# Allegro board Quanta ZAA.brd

Outline 244.9 x 198.7 mm; copper layers: TOP, SVCC, IN1, IN2, SGND, BOTTOM. Coordinates in mm from the lower left corner of the outline.

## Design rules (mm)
constraint set DEFAULT: min track width 0.127
net group DFP-S4W4.5(4.5)-2B: nets HDMI_DDCCLK_SW HDMI_DDCDATA_SW
net group DFP-S4W4.5(4.5)-T2B: nets HDMI_DDCCLK_MB HDMI_DDCDATA_MB
net group DFP-S4W4.5-T: nets USBP0+_R USBP0-_R
net group DFP-S4W4.5-TB: nets USBP0+_C USBP0-_C
net group DFP-S5W5.5(5.5)-2B: nets LAN_XTAL2 RTC_X1
net group DFP-S10W5(5.5: nets VCORE_SENSE VCORESS_SENSE
net group DFP-S20(10)W16(18)-T2B: nets VGA_VCCSENSE VGA_VSSSENSE
net group W5(5)-T2B: nets CPU_DRAMRST# DDR3_DRAMRST#
net group W5(5)-T12B: nets M_A_DQS8 M_A_DQS#8
net group W5.5(5.5)-T12B: nets DMIC_CLK_L DMIC_DAT_L
net group W12-T12B: nets PCIE_RCOMPN PCIE_RCOMPP
net group W25-T12B: nets +3V_RTC VCCRTC_2
net group DFP-S4(4)W4.5(4.5)-2B: nets AUX_CH_N AUX_CH_P C_PEG_TX0 C_PEG_TX1 C_PEG_TX2 C_PEG_TX3 C_PEG_TX#0 C_PEG_TX#1 C_PEG_TX#2 C_PEG_TX#3 CLK_PCIE_LANN CLK_PCIE_LANP CLK_PCIE_VGA CLK_PCIE_VGA# CLK_PCIE_WLANN CLK_PCIE_WLANP CRT_AUXN CRT_AUXP CRT_TXN0 CRT_TXN1 CRT_TXP0 CRT_TXP1 DDI2_AUXN DDI2_AUXP DDI2_TXN0 DDI2_TXN1 DDI2_TXP0 DDI2_TXP1 EDP_AUX#_C EDP_AUX_C EDP_AUXN EDP_AUXP EDP_TXN0 EDP_TXN0_C EDP_TXN1 EDP_TXN1_C EDP_TXN2 EDP_TXN2_C EDP_TXN3 EDP_TXN3_C EDP_TXP0 EDP_TXP0_C EDP_TXP1 EDP_TXP1_C EDP_TXP2 EDP_TXP2_C EDP_TXP3 EDP_TXP3_C INT_HDMICLK+ INT_HDMICLK+_C_R INT_HDMICLK- INT_HDMICLK-_C_R INT_HDMITX0N INT_HDMITX0N_C_R INT_HDMITX0P INT_HDMITX0P_C_R INT_HDMITX1N INT_HDMITX1N_C_R INT_HDMITX1P INT_HDMITX1P_C_R INT_HDMITX2N INT_HDMITX2N_C_R INT_HDMITX2P INT_HDMITX2P_C_R LANE0_N LANE0_P LANE1_N LANE1_P NGFF_SSD_CLK NGFF_SSD_CLK# NGFF_SSD_CLK#_C NGFF_SSD_CLK_C PCIE_RX5+_LAN PCIE_RX5+_LAN_C PCIE_RX5-_LAN PCIE_RX5-_LAN_C PCIE_RX6+_WLAN PCIE_RX6-_WLAN PCIE_TX5+ PCIE_TX5+_LAN PCIE_TX5- PCIE_TX5-_LAN PCIE_TX6+ PCIE_TX6+_WLAN PCIE_TX6- PCIE_TX6-_WLAN PEG_RX0 PEG_RX1 PEG_RX2 PEG_RX3 PEG_RX#0 PEG_RX#1 PEG_RX#2 PEG_RX#3 PEG_RXN0_C PEG_RXN1_C PEG_RXN2_C PEG_RXN3_C PEG_RXP0_C PEG_RXP1_C PEG_RXP2_C PEG_RXP3_C PEG_TX0 PEG_TX1 PEG_TX2 PEG_TX3 PEG_TX#0 PEG_TX#1 PEG_TX#2 PEG_TX#3 SATA_RXN0 SATA_RXN1 SATA_RXN1_C SATA_RXN3/PEG_RXN9_L0 SATA_RXN3/PEG_RXN9_L0_N SATA_RXN3/PEG_RXN10_L1 SATA_RXN3/PEG_RXN10_L1_N SATA_RXP0 SATA_RXP1 SATA_RXP1_C SATA_RXP3/PEG_RXP9_L0 SATA_RXP3/PEG_RXP9_L0_N SATA_RXP3/PEG_RXP10_L1 SATA_RXP3/PEG_RXP10_L1_N SATA_TXN0 SATA_TXN1 SATA_TXN1_C SATA_TXN3/PEG_TXN9_L0 SATA_TXN3/PEG_TXN9_L0_N SATA_TXN3/PEG_TXN10_L1 SATA_TXN3/PEG_TXN10_L1_N SATA_TXP0 SATA_TXP1 SATA_TXP1_C SATA_TXP3/PEG_TXP9_L0 SATA_TXP3/PEG_TXP9_L0_N SATA_TXP3/PEG_TXP10_L1 SATA_TXP3/PEG_TXP10_L1_N USBP0+ USBP0- USBP1+ USBP1- USBP2+ USBP2- USBP3+ USBP3- USBP4+ USBP4- USBP6+ USBP6+_R USBP6- USBP6-_R
net group DFP-S4(4)W4.5(4.5)-T2B: nets M_B_CLK0 M_B_CLK0# M_B_CLK1 M_B_CLK1# USB2_TYPC_7N_C USB2_TYPC_7P_C USB3_RXN0 USB3_RXN0_R USB3_RXN1 USB3_RXN1_R USB3_RXN2 USB3_RXN3 USB3_RXP0 USB3_RXP0_R USB3_RXP1 USB3_RXP1_R USB3_RXP2 USB3_RXP3 USB3_TXN0 USB3_TXN0_C USB3_TXN0_R USB3_TXN1 USB3_TXN1_C USB3_TXN1_R USB3_TXN2 USB3_TXN3 USB3_TXP0 USB3_TXP0_C USB3_TXP0_R USB3_TXP1 USB3_TXP1_C USB3_TXP1_R USB3_TXP2 USB3_TXP3 USB3_TYPC_RX2N_C USB3_TYPC_RX2N_C_RE USB3_TYPC_RX2N_RE USB3_TYPC_RX2P_C USB3_TYPC_RX2P_C_RE USB3_TYPC_RX2P_RE USB3_TYPC_RX3N_C USB3_TYPC_RX3N_C_RE USB3_TYPC_RX3N_RE USB3_TYPC_RX3P_C USB3_TYPC_RX3P_C_RE USB3_TYPC_RX3P_RE USB3_TYPC_TX2N_C USB3_TYPC_TX2N_C_RE USB3_TYPC_TX2N_R USB3_TYPC_TX2N_RE USB3_TYPC_TX2P_C USB3_TYPC_TX2P_C_RE USB3_TYPC_TX2P_R USB3_TYPC_TX2P_RE USB3_TYPC_TX3N_C USB3_TYPC_TX3N_C_RE USB3_TYPC_TX3N_R USB3_TYPC_TX3N_RE USB3_TYPC_TX3P_C USB3_TYPC_TX3P_C_RE USB3_TYPC_TX3P_R USB3_TYPC_TX3P_RE USBP1+_R USBP1-_R USBP7+ USBP7- USBP8+_PI3 USBP8+_R_PI3 USBP8-_PI3 USBP8-_R_PI3
net group DFP-S4(4)W4.5(4.5)-T12B: nets M_A_CLK0 M_A_CLK0# M_A_CLK1 M_A_CLK1#
net group DFP-S4.5(4.5)W5(5)-T2B: nets M_B_DQS0 M_B_DQS1 M_B_DQS2 M_B_DQS3 M_B_DQS4 M_B_DQS5 M_B_DQS6 M_B_DQS7 M_B_DQS#0 M_B_DQS#1 M_B_DQS#2 M_B_DQS#3 M_B_DQS#4 M_B_DQS#5 M_B_DQS#6 M_B_DQS#7
net group DFP-S4.5(4.5)W5(5)-T12B: nets M_A_DQS0 M_A_DQS1 M_A_DQS2 M_A_DQS3 M_A_DQS4 M_A_DQS5 M_A_DQS6 M_A_DQS7 M_A_DQS#0 M_A_DQS#1 M_A_DQS#2 M_A_DQS#3 M_A_DQS#4 M_A_DQS#5 M_A_DQS#6 M_A_DQS#7
net group DFP-S4.5(4.5)W5.5(5.5)-T12B: nets VMA_CLK0 VMA_CLK0# VMA_CLK1 VMA_CLK1# VMA_WCK01 VMA_WCK01# VMA_WCK23 VMA_WCK23# VMA_WCK45 VMA_WCK45# VMA_WCK67 VMA_WCK67# VMB_CLK0 VMB_CLK0# VMB_CLK1 VMB_CLK1# VMB_WCK01 VMB_WCK01# VMB_WCK23 VMB_WCK23# VMB_WCK45 VMB_WCK45# VMB_WCK67 VMB_WCK67#
net group DFP-S4W4.5-B: nets SATA_RXN0_C SATA_RXP0_C SATA_TXN0_C SATA_TXP0_C
net group DFP-S6W5(5.5)-T2B: nets 2ND_MBCLK 2ND_MBDATA CLK_SCLK CLK_SDATA GFX_SCL GFX_SDA I2C0_SCL I2C0_SDA I2C1_SCL I2C1_SCL_C I2C1_SDA I2C1_SDA_C I2C_TP_SCL_R I2C_TP_SDA_R MBCLK MBDATA N17046941 N17047425 PCH_MBCLK0_R PCH_MBDAT0_R SMB_ME1_CLK SMB_ME1_DAT TPCLK TPCLK_R TPDATA TPDATA_R
net group DFP-S7.5(7)W4(4)-2B: nets MDI_0+ MDI_0- MDI_1+ MDI_1- MDI_2+ MDI_2- MDI_3+ MDI_3-
net group DFP-S7.5(7)W4(4)-T2B: nets INT_HDMICLK+_C INT_HDMICLK-_C INT_HDMITX0N_C INT_HDMITX0P_C INT_HDMITX1N_C INT_HDMITX1P_C INT_HDMITX2N_C INT_HDMITX2P_C LAN_MX0+ LAN_MX0- LAN_MX1+ LAN_MX1- LAN_MX2+ LAN_MX2- LAN_MX3+ LAN_MX3-
net group DFP-S10W5(5.5)-T2B: nets VCCGT_SENSE VSA_SENSE VSASS_SENSE VSSGT_SENSE
net group DFP-S15W5.5(5.5)-2B: nets LAN_XTALI RTC_X2 XTAL24_IN XTAL24_OUT XTAL27_IN XTAL27_OUT
net group GND: nets GND
net group W4.5(4.5)-T12B: nets ACZ_SDIN HDA_BCLK_R HDA_RST#_R HDA_SDO_R HDA_SYNC_R HDMI_MB_HPD HDMI_MB_HPD_R HP_DET_CN INT_HDMI_HPD PCH_AZ_CODEC_BITCLK PCH_AZ_CODEC_RST# PCH_AZ_CODEC_SDIN0 PCH_AZ_CODEC_SDOUT PCH_AZ_CODEC_SYNC SD_CLK_R SP1 SP2 SP3 SP3=SD_CLK=MS_D0 SP4 SP5 SP6 SP6=SD_D2=MS_CLK SP7 SP8 USBCOMP
net group W4.5-T2B: nets CLK_PCIE_LAN_REQ# CLK_PCIE_REQ0# CLK_PCIE_REQ2# CLK_PCIE_REQ4# CLK_PCIE_REQ5# CLK_PEGA_REQ# PCIE_CLKREQ_WLAN# PCIE_REQ_LAN#_R PEX_CLKREQ# WLAN_CLKREQ#
net group W5(5.5)-2B: nets CPU_THRMTRIP# CRT_B1 CRT_BLU CRT_G1 CRT_GRE CRT_R1 CRT_RED ISL95857_SCLK ISL95857_SDA
net group W5(5.5)-T2B: nets CRTHSYNC CRTVSYNC HSYNC IMVP_PWRGD LPC_LAD0 LPC_LAD0_C LPC_LAD1 LPC_LAD1_C LPC_LAD2 LPC_LAD2_C LPC_LAD3 LPC_LAD3_C LPC_LFRAME# LPC_LFRAME#_C M_B_DQ0 M_B_DQ1 M_B_DQ2 M_B_DQ3 M_B_DQ4 M_B_DQ5 M_B_DQ6 M_B_DQ7 M_B_DQ8 M_B_DQ9 M_B_DQ10 M_B_DQ11 M_B_DQ12 M_B_DQ13 M_B_DQ14 M_B_DQ15 M_B_DQ16 M_B_DQ17 M_B_DQ18 M_B_DQ19 M_B_DQ20 M_B_DQ21 M_B_DQ22 M_B_DQ23 M_B_DQ24 M_B_DQ25 M_B_DQ26 M_B_DQ27 M_B_DQ28 M_B_DQ29 M_B_DQ30 M_B_DQ31 M_B_DQ32 M_B_DQ33 M_B_DQ34 M_B_DQ35 M_B_DQ36 M_B_DQ37 M_B_DQ38 M_B_DQ39 M_B_DQ40 M_B_DQ41 M_B_DQ42 M_B_DQ43 M_B_DQ44 M_B_DQ45 M_B_DQ46 M_B_DQ47 M_B_DQ48 M_B_DQ49 M_B_DQ50 M_B_DQ51 M_B_DQ52 M_B_DQ53 M_B_DQ54 M_B_DQ55 M_B_DQ56 M_B_DQ57 M_B_DQ58 M_B_DQ59 M_B_DQ60 M_B_DQ61 M_B_DQ62 M_B_DQ63 PCH_SPI_CLK PCH_SPI_CS0# PCH_SPI_IO2 PCH_SPI_IO3 PCH_SPI_SI PCIE_CLKREQ_NGFF_SSD# PCIE_CLKREQ_NGFF_SSD#_R SPI_CLK_8M SPI_HOLD_IO3_ME SPI_SI_8M SPI_SO_8M SPI_WP_IO2_ME VCCST_PWRGD VCCST_PWRGD_R VSYNC
net group W5(5.5)-T12B: nets CRT_HPD DMIC_CLK DMIC_CLK_L1 DMIC_CLK_L2 DMIC_CLK_L_R0 DMIC_CLK_L_R1 DMIC_CLK_L_R2 DMIC_DAT DMIC_DAT_L1 DMIC_DAT_L2 DMIC_DAT_L_R0 DMIC_DAT_L_R1 DMIC_DAT_L_R2 M_A_DQ0 M_A_DQ1 M_A_DQ2 M_A_DQ3 M_A_DQ4 M_A_DQ5 M_A_DQ6 M_A_DQ7 M_A_DQ8 M_A_DQ9 M_A_DQ10 M_A_DQ11 M_A_DQ12 M_A_DQ13 M_A_DQ14 M_A_DQ15 M_A_DQ16 M_A_DQ17 M_A_DQ18 M_A_DQ19 M_A_DQ20 M_A_DQ21 M_A_DQ22 M_A_DQ23 M_A_DQ24 M_A_DQ25 M_A_DQ26 M_A_DQ27 M_A_DQ28 M_A_DQ29 M_A_DQ30 M_A_DQ31 M_A_DQ32 M_A_DQ33 M_A_DQ34 M_A_DQ35 M_A_DQ36 M_A_DQ37 M_A_DQ38 M_A_DQ39 M_A_DQ40 M_A_DQ41 M_A_DQ42 M_A_DQ43 M_A_DQ44 M_A_DQ45 M_A_DQ46 M_A_DQ47 M_A_DQ48 M_A_DQ49 M_A_DQ50 M_A_DQ51 M_A_DQ52 M_A_DQ53 M_A_DQ54 M_A_DQ55 M_A_DQ56 M_A_DQ57 M_A_DQ58 M_A_DQ59 M_A_DQ60 M_A_DQ61 M_A_DQ62 M_A_DQ63
net group W5(5.5: nets CATERR# DDR_VTTT_PG_CTRL DNBSWON# DPWROK_R H_PECI H_PROCHOT# H_PROCHOT#_R INTRUDER# PCH_PWRBTN# PCH_RSMRST# PCI_PLTRST# PEGX_RST# PEX_TERMP PLTRST# PWM-VID RSMRST# RTC_RST# SIO_RCIN# SRTC_RST# SYS_PWROK SYS_PWROK_R SYS_RESET# TESTMODE THRMTRIP# XDP_BPM#0 XDP_BPM#1
net group W5-TB: nets H_CPU_SVIDART# H_CPU_SVIDCLK H_CPU_SVIDDAT VR_SVID_ALERT#_VCORE
net group W5.5(5.5)-2B: nets CLK_PCI_EC CLK_PCI_LPC CLK_PCI_LPC_C PCLK_TPM
net group W6(6.7)-T12B: nets FBA_CMD0 FBA_CMD1 FBA_CMD2 FBA_CMD3 FBA_CMD4 FBA_CMD5 FBA_CMD6 FBA_CMD7 FBA_CMD8 FBA_CMD9 FBA_CMD10 FBA_CMD11 FBA_CMD12 FBA_CMD13 FBA_CMD14 FBA_CMD15 FBA_CMD16 FBA_CMD17 FBA_CMD18 FBA_CMD19 FBA_CMD20 FBA_CMD21 FBA_CMD22 FBA_CMD23 FBA_CMD24 FBA_CMD25 FBA_CMD26 FBA_CMD27 FBA_CMD28 FBA_CMD29 FBA_CMD30 FBA_CMD31 FBA_DBI0 FBA_DBI1 FBA_DBI2 FBA_DBI3 FBA_DBI4 FBA_DBI5 FBA_DBI6 FBA_DBI7 FBA_EDC0 FBA_EDC1 FBA_EDC2 FBA_EDC3 FBA_EDC4 FBA_EDC5 FBA_EDC6 FBA_EDC7 FBB_CMD0 FBB_CMD1 FBB_CMD2 FBB_CMD3 FBB_CMD4 FBB_CMD5 FBB_CMD6 FBB_CMD7 FBB_CMD8 FBB_CMD9 FBB_CMD10 FBB_CMD11 FBB_CMD12 FBB_CMD13 FBB_CMD14 FBB_CMD15 FBB_CMD16 FBB_CMD17 FBB_CMD18 FBB_CMD19 FBB_CMD20 FBB_CMD21 FBB_CMD22 FBB_CMD23 FBB_CMD24 FBB_CMD25 FBB_CMD26 FBB_CMD27 FBB_CMD28 FBB_CMD29 FBB_CMD30 FBB_CMD31 FBB_DBI0 FBB_DBI1 FBB_DBI2 FBB_DBI3 FBB_DBI4 FBB_DBI5 FBB_DBI6 FBB_DBI7 FBB_EDC0 FBB_EDC1 FBB_EDC2 FBB_EDC3 FBB_EDC4 FBB_EDC5 FBB_EDC6 FBB_EDC7 VMA_DQ0 VMA_DQ1 VMA_DQ2 VMA_DQ3 VMA_DQ4 VMA_DQ5 VMA_DQ6 VMA_DQ7 VMA_DQ8 VMA_DQ9 VMA_DQ10 VMA_DQ11 VMA_DQ12 VMA_DQ13 VMA_DQ14 VMA_DQ15 VMA_DQ16 VMA_DQ17 VMA_DQ18 VMA_DQ19 VMA_DQ20 VMA_DQ21 VMA_DQ22 VMA_DQ23 VMA_DQ24 VMA_DQ25 VMA_DQ26 VMA_DQ27 VMA_DQ28 VMA_DQ29 VMA_DQ30 VMA_DQ31 VMA_DQ32 VMA_DQ33 VMA_DQ34 VMA_DQ35 VMA_DQ36 VMA_DQ37 VMA_DQ38 VMA_DQ39 VMA_DQ40 VMA_DQ41 VMA_DQ42 VMA_DQ43 VMA_DQ44 VMA_DQ45 VMA_DQ46 VMA_DQ47 VMA_DQ48 VMA_DQ49 VMA_DQ50 VMA_DQ51 VMA_DQ52 VMA_DQ53 VMA_DQ54 VMA_DQ55 VMA_DQ56 VMA_DQ57 VMA_DQ58 VMA_DQ59 VMA_DQ60 VMA_DQ61 VMA_DQ62 VMA_DQ63 VMB_DQ0 VMB_DQ1 VMB_DQ2 VMB_DQ3 VMB_DQ4 VMB_DQ5 VMB_DQ6 VMB_DQ7 VMB_DQ8 VMB_DQ9 VMB_DQ10 VMB_DQ11 VMB_DQ12 VMB_DQ13 VMB_DQ14 VMB_DQ15 VMB_DQ16 VMB_DQ17 VMB_DQ18 VMB_DQ19 VMB_DQ20 VMB_DQ21 VMB_DQ22 VMB_DQ23 VMB_DQ24 VMB_DQ25 VMB_DQ26 VMB_DQ27 VMB_DQ28 VMB_DQ29 VMB_DQ30 VMB_DQ31 VMB_DQ32 VMB_DQ33 VMB_DQ34 VMB_DQ35 VMB_DQ36 VMB_DQ37 VMB_DQ38 VMB_DQ39 VMB_DQ40 VMB_DQ41 VMB_DQ42 VMB_DQ43 VMB_DQ44 VMB_DQ45 VMB_DQ46 VMB_DQ47 VMB_DQ48 VMB_DQ49 VMB_DQ50 VMB_DQ51 VMB_DQ52 VMB_DQ53 VMB_DQ54 VMB_DQ55 VMB_DQ56 VMB_DQ57 VMB_DQ58 VMB_DQ59 VMB_DQ60 VMB_DQ61 VMB_DQ62 VMB_DQ63
net group W7.5(8.5)-T2B: nets M_B_A0 M_B_A1 M_B_A2 M_B_A3 M_B_A4 M_B_A5 M_B_A6 M_B_A7 M_B_A8 M_B_A9 M_B_A10 M_B_A11 M_B_A12 M_B_A13 M_B_ACT# M_B_CAS# M_B_CKE0 M_B_CKE1 M_B_CS#0 M_B_CS#1 M_B_ODT0_DIMM M_B_ODT1_DIMM M_B_PARITY M_B_RAS# M_B_WE#
net group W7.5(8.5)-T12B: nets M_A_A0 M_A_A1 M_A_A2 M_A_A3 M_A_A4 M_A_A5 M_A_A6 M_A_A7 M_A_A8 M_A_A9 M_A_A10 M_A_A11 M_A_A12 M_A_A13 M_A_ACT# M_A_ALERT# M_A_CAS# M_A_CKE0 M_A_CKE1 M_A_CS#0 M_A_CS#1 M_A_ODT0_DIMM M_A_ODT1_DIMM M_A_PARITY M_A_RAS# M_A_WE# M_B_ALERT# M_B_BA#0 M_B_BA#1 M_B_BG#0 M_B_BG#1
net group W7.5(8.5: nets M_A_BA#0 M_A_BA#1 M_A_BG#0 M_A_BG#1
net group W10-T12B: nets +1V_VCCST +2.5V +VCCPLL +VCCPRTC +VCCSTG HDMI_5V NV_PLLVDD RSET
net group W15-T12B: nets +TPVDD +VDDQC FB_CAL_PD_VDDQ HP-L2 HP-L3 HP-R2 HP-R3 HP_JD# LINE1-L LINE1-R LINE1-VREFO-L LINE1-VREFO-R MIC2-VREFO SENSEA SM_RCOMP_0 SM_RCOMP_1 SM_RCOMP_2 VDD33/18
net group W20-12B: nets EDP_RCOMP
net group W20-T12B: nets 3V_LR +1.5VA +3V3_SD_SW +3V_MAIN +3V_S5 +5VA +AZA_VDD +VCCPDSW_3P3 +VREF_CA_CPU +VREFDQ_SA_M3 +VREFDQ_SB_M3 +WL_VDD CFG_RCOMP DVDD_IO FB_CAL_TERM_GND PEX_PLLVDD PVDD SLEEVE_R VDD_DAC_33
net group W30-T12B: nets +3V_EC +3VPCU_EC +3VPCU_ECPLL +5V_KB +A3VPCU +VDDQ AVCC33 CCD_PWR CRTVDD5 ECAGND EVDD10 LAN_MCT0 LAN_MCT1 LAN_MCT2 LAN_MCT3 RING2_R TERM9 TH_FAN_POWER TP_PWR
net group W40-T2B: nets LCDVCC
net group W40-T12B: nets DDR_VTTREF L_SPK+ L_SPK+_1 L_SPK- L_SPK-_1 LANVCC R_SPK+ R_SPK+_1 R_SPK- R_SPK-_1 REGOUT RING2 SLEEVE VDD10 VDDREG
net group W60-2B: nets V_BLIGHT
net group W60-T12B: nets +3V_LAN
net group W80-T12B: nets +3V3_SATA_N1 +5V_HDD +5V_ODD USBPWR0
net group W99-T12B: nets +1.05V_GFX +1.35V_GFX +TYPEC_VBUS +TYPEC_VBUS_C +VCCEOPIO +VCCOPC +VGPU_CORE LCDVCC_R USBPWR1 USBPWRD2

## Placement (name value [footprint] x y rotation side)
BT1  bat_conn  [BAT-AP-AAA-BAT-054-K01-2P-SMT]  69.91 35.45 90 top
C2  0.1u/16v_4  [C0402]  124.14 167.53 270 bottom
C4  0.1u/16v_4  [C0402]  123.12 167.53 270 bottom
C7  4.7u/25v_8  [C0805]  111.31 163.04 0 bottom
C8  0.1u/16v_4  [C0402]  125.28 171.98 315 bottom
C9  1000p/50v_4  [C0402]  118.01 160.17 270 top
C10  0.1u/16v_4  [C0402]  124.64 171.34 315 bottom
C12  0.1u/16v_4  [C0402]  126.55 173.25 315 bottom
C13  0.1u/16v_4  [C0402]  125.91 172.61 315 bottom
C16  1000p/50v_4  [C0402]  116.77 168.17 270 top
C19  ev_a@0.1u/16v_4  [C0402]  195.13 166.14 90 top
C27  0.1u/10v_4_x7r  [C0402]  117.66 168.17 270 top
C29  *2.2u/10v_8  [C0805]  116.44 159.2 270 bottom
C30  22u/6.3v_8  [C0805]  116.44 159.2 90 top
C33  *0.1u/16v_4  [C0402]  113.21 159.91 270 bottom
C34  0.01u/50v_4  [C0402]  114.99 159.91 90 bottom
C35  0.1u/16v_4  [C0402]  114.1 159.91 270 bottom
C41  1u/6.3v_4  [C0402]  110.29 161.56 180 bottom
C73  ev@330u_2.5v_3528  [C3528]  225.61 121.56 90 bottom
C114  10u/6.3v_4  [C0402]  138.59 131.59 90 top
C136  1000p/50v_4  [C0402]  96.32 126.64 180 bottom
C144  d22@47u/6.3v_8  [C0805]  129.47 137.94 90 bottom
C148  10u/6.3v_4  [C0402]  110.97 139.45 180 top
C150  d22@47u/6.3v_8  [C0805]  131.37 137.94 90 bottom
C151  10u/6.3v_4  [C0402]  110.97 138.43 180 top
C155  10u/6.3v_4  [C0402]  110.97 136.91 180 top
C157  10u/6.3v_4  [C0402]  137.67 131.59 90 top
C158  10u/6.3v_4  [C0402]  110.97 135.89 180 top
C161  10u/6.3v_4  [C0402]  110.97 134.88 180 top
C164  0.1u/16v_4  [C0402]  84.26 121.94 270 bottom
C165  10u/6.3v_4  [C0402]  136.71 131.59 90 top
C168  *0.1u/16v_4  [C0402]  180.12 35.43 270 top
C169  bl@4.7u/10v_6  [C0603]  223.45 140.99 270 bottom
C170  bl@0.01u/50v_4  [C0402]  224.59 140.61 270 bottom
C171  d10@22u/6.3v_6  [C0603]  91.17 113.18 270 bottom
C172  1u/6.3v_4  [C0402]  133.15 127.91 180 bottom
C173  1u/6.3v_4  [C0402]  139.88 119.02 270 top
C174  1u/6.3v_4  [C0402]  133.97 124.66 270 top
C176  1u/6.3v_4  [C0402]  134.88 124.66 270 top
C178  d10@22u/6.3v_6  [C0603]  100.51 121.56 270 top
C179  1u/6.3v_4  [C0402]  140.8 119.02 270 top
C181  1u/6.3v_4  [C0402]  119.15 123.79 180 top
C182  47u/6.3v_8  [C0805]  144.81 125.34 0 top
C184  1u/6.3v_4  [C0402]  115.14 116.58 0 top
C185  10u/6.3v_4  [C0402]  97.29 113.2 90 top
C186  10u/6.3v_4  [C0402]  96.27 113.2 90 top
C187  bl@2.2u/6.3v_6  [C0603]  228.91 144.04 0 bottom
C188  1u/6.3v_4  [C0402]  100.01 114.12 180 top
C189  1u/6.3v_4  [C0402]  119.15 122.83 180 top
C190  d22@47u/6.3v_8  [C0805]  84.46 128.65 270 bottom
C191  1u/6.3v_4  [C0402]  144.99 123.92 0 top
C192  1u/6.3v_4  [C0402]  142.17 118.76 270 top
C193  1u/6.3v_4  [C0402]  98.66 115.46 270 top
C194  1u/6.3v_4  [C0402]  100.56 117.98 90 top
C195  1u/6.3v_4  [C0402]  97.69 115.46 270 top
C196  1u/6.3v_2  [C0201]  121.9 124.12 90 top
C197  1u/6.3v_4  [C0402]  93.12 113.23 270 top
C198  1u/6.3v_4  [C0402]  100.95 116.1 0 top
C199  d22@47u/6.3v_8  [C0805]  87.76 129.1 0 bottom
C200  1u/6.3v_4  [C0402]  121.57 108 180 top
C201  1u/6.3v_4  [C0402]  123.21 119.64 0 top
C202  d10@22u/6.3v_6  [C0603]  114.48 113.61 0 top
C203  d10@22u/6.3v_6  [C0603]  122.82 110.1 0 top
C204  1u/6.3v_4  [C0402]  101.53 117.98 90 top
C205  1u/6.3v_4  [C0402]  107.94 100.65 180 top
C206  1u/6.3v_4  [C0402]  99.62 115.46 270 top
C207  1u/6.3v_4  [C0402]  124.57 118.71 180 top
C209  1u/6.3v_4  [C0402]  122.84 118.71 0 top
C210  d10@22u/6.3v_6  [C0603]  114.48 112.31 0 top
C212  1u/6.3v_4  [C0402]  116.08 118.08 270 top
C214  1u/6.3v_4  [C0402]  120.1 109.85 270 top
C215  1u/6.3v_4  [C0402]  134.65 149.09 90 top
C216  1u/6.3v_4  [C0402]  125.11 117.1 180 top
C217  1u/6.3v_4  [C0402]  144.07 118.76 270 top
C218  10u/6.3v_4  [C0402]  96.65 118.89 270 top
C219  d10@22u/6.3v_6  [C0603]  122.65 116.08 0 top
C221  10u/6.3v_4  [C0402]  125.19 116.13 0 top
C222  1u/6.3v_4  [C0402]  133.69 149.09 90 top
C223  10u/6.3v_4  [C0402]  95.64 118.89 270 top
C224  d10@22u/6.3v_6  [C0603]  117.91 116.05 180 top
C225  *1u/6.3v_4  [C0402]  143.19 118.76 270 top
C226  d10@22u/6.3v_6  [C0603]  122.66 117.42 0 top
C227  1u/6.3v_4  [C0402]  120.05 119.68 90 top
C228  1u/6.3v_4  [C0402]  132.7 149.09 90 top
C229  10u/6.3v_4  [C0402]  125.19 115.19 0 top
C230  1u/6.3v_4  [C0402]  146.23 112.67 0 top
C232  10u/6.3v_4  [C0402]  95.26 113.2 90 top
C233  d10@22u/6.3v_6  [C0603]  117.91 114.69 180 top
C235  1u/6.3v_2  [C0201]  117.81 109.01 90 top
C236  d10@22u/6.3v_6  [C0603]  118.01 117.44 180 top
C237  1u/6.3v_4  [C0402]  117.91 110.79 180 top
C238  10u/6.3v_4  [C0402]  125.19 114.18 0 top
C239  1u/6.3v_4  [C0402]  108.24 103.19 0 top
C240  1u/6.3v_4  [C0402]  99.6 117.98 90 top
C241  1u/6.3v_4  [C0402]  102.5 117.98 90 top
C242  1u/6.3v_4  [C0402]  126.9 114.55 0 top
C243  d10@22u/6.3v_6  [C0603]  117.91 113.31 180 top
C244  0.1u/16v_4  [C0402]  32.7 71.27 270 top
C245  1u/6.3v_2  [C0201]  115.37 117.93 90 top
C246  1u/6.3v_4  [C0402]  121.01 109.85 270 top
C247  10u/6.3v_4  [C0402]  125.19 113.16 0 top
C248  d22@47u/6.3v_8  [C0805]  80.14 129.48 180 bottom
C249  1u/6.3v_4  [C0402]  127.4 112.73 0 top
C250  1u/6.3v_4  [C0402]  143.95 112.67 180 top
C251  d10@22u/6.3v_6  [C0603]  122.63 111.49 0 top
C252  1u/6.3v_4  [C0402]  119.18 109.85 270 top
C254  10u/6.3v_4  [C0402]  125.19 112.22 0 top
C255  d10@22u/6.3v_6  [C0603]  117.91 111.96 180 top
C256  1u/6.3v_4  [C0402]  151.95 109.49 90 top
C257  10u/6.3v_4  [C0402]  122.83 113.59 180 top
C258  10u/6.3v_4  [C0402]  126.55 141.37 90 top
C259  10u/6.3v_4  [C0402]  122.83 112.58 180 top
C260  1u/6.3v_4  [C0402]  127.4 111.76 0 top
C261  1u/6.3v_4  [C0402]  152.96 109.49 270 top
C262  1u/6.3v_4  [C0402]  120.12 108.15 90 top
C263  10u/6.3v_4  [C0402]  125.19 111.26 0 top
C264  1u/6.3v_4  [C0402]  116.02 110.7 90 top
C265  *1u/6.3v_4  [C0402]  144.33 110.38 0 top
C266  1u/6.3v_4  [C0402]  115.06 110.42 90 top
C267  1u/6.3v_4  [C0402]  127.4 110.8 0 top
C268  1u/6.3v_4  [C0402]  154.87 109.49 90 top
C269  1u/6.3v_2  [C0201]  117.94 110.03 0 top
C270  *1u/6.3v_4  [C0402]  153.98 109.49 90 top
C272  d10@22u/6.3v_6  [C0603]  122.74 114.75 0 top
C273  d10@22u/6.3v_6  [C0603]  120.67 123.62 270 top
C274  gt3@22u/6.3v_6  [C0603]  96.7 113.18 270 bottom
C275  gt3@22u/6.3v_6  [C0603]  95.31 113.18 270 bottom
C276  gt3@22u/6.3v_6  [C0603]  90.79 118.16 180 top
C277  gt3@22u/6.3v_6  [C0603]  114.76 114.98 0 top
C278  1u/6.3v_4  [C0402]  127.29 109.78 0 top
C279  gt3@10u/6.3v_4  [C0402]  114.09 110.34 270 top
C280  gt3@10u/6.3v_4  [C0402]  112.06 110.34 270 top
C281  gt3@10u/6.3v_4  [C0402]  113.07 110.34 270 top
C282  d10@22u/6.3v_6  [C0603]  117.85 119.16 180 top
C283  10u/6.3v_4  [C0402]  124.58 109.89 270 top
C284  10u/6.3v_4  [C0402]  124.95 108.05 180 top
C285  1u/6.3v_2  [C0201]  119.23 124.58 0 top
C286  10u/6.3v_4  [C0402]  117.06 109.48 270 top
C288  10u/6.3v_4  [C0402]  127.21 113.58 180 top
C289  d10@22u/6.3v_6  [C0603]  118.67 107.16 270 top
C290  gt3@10u/6.3v_4  [C0402]  111.04 107.95 180 top
C291  gt3@10u/6.3v_4  [C0402]  113.07 107.95 0 top
C292  *1u/6.3v_4  [C0402]  155.76 109.49 90 top
C297  1u/6.3v_4  [C0402]  122.99 107.13 180 top
C298  1u/6.3v_4  [C0402]  125.58 109.89 90 top
C299  1u/6.3v_4  [C0402]  117.25 108.05 0 top
C300  *220p/50v_4  [C0402]  10.85 84.73 90 top
C301  0.1u/16v_4  [C0402]  10.9 83 90 bottom
C302  gt3@22u/6.3v_6  [C0603]  96.7 118.64 90 bottom
C303  gt3@22u/6.3v_6  [C0603]  95.31 118.64 90 bottom
C304  *0.1u/16v_4  [C0402]  12.88 84.73 90 top
C305  *0.22u/6.3v_4  [C0402]  11.87 84.73 270 top
C307  gt3@22u/6.3v_6  [C0603]  89.11 118.66 90 bottom
C308  1u/6.3v_4  [C0402]  126.71 103.46 270 top
C310  gt3@22u/6.3v_6  [C0603]  89.9 113.18 270 bottom
C311  1u/6.3v_4  [C0402]  122.14 102.85 90 top
C312  1u/6.3v_4  [C0402]  118.71 102.87 90 top
C313  1u/6.3v_4  [C0402]  119.86 102.87 270 top
C314  *0.1u/16v_4  [C0402]  164.27 75.53 0 top
C315  0.1u/16v_4  [C0402]  29.27 71.77 0 top
C316  gt3@10u/6.3v_4  [C0402]  94.67 118.89 270 top
C317  gt3@10u/6.3v_4  [C0402]  94.24 113.2 90 top
C318  10u/6.3v_4  [C0402]  117.19 102.24 180 top
C319  *5.6p/16v_4  [C0402]  12.12 78 90 top
C320  5.6p/16v_4  [C0402]  15.93 77.49 270 top
C321  2.2u_6  [C0603]  65.86 116.34 180 bottom
C322  1u/6.3v_4  [C0402]  133.31 101.62 270 top
C323  10u/6.3v_4  [C0402]  124.44 101.44 90 top
C324  gt3@10u/6.3v_4  [C0402]  93.58 118.89 270 top
C325  10u/6.3v_4  [C0402]  129.6 97.3 90 bottom
C326  10u/6.3v_4  [C0402]  119.98 101.35 0 top
C327  10u/6.3v_4  [C0402]  126.73 101.67 90 top
C328  10u/6.3v_4  [C0402]  122.52 101.33 180 top
C329  0.1u/16v_4  [C0402]  29.27 70.89 0 top
C330  *ioac@15p/50v_4  [C0402]  229.29 104.54 270 top
C331  0.1u/16v_4  [C0402]  28 69.74 0 top
C332  0.1u/16v_4  [C0402]  165.11 85.41 0 bottom
C333  *5.6p/16v_4  [C0402]  12.12 75.08 270 top
C334  5.6p/16v_4  [C0402]  15.93 75.61 90 top
C335  0.1u/16v_4  [C0402]  28 68.85 0 top
C336  *5.6p/16v_4  [C0402]  12.12 72.54 270 top
C337  5.6p/16v_4  [C0402]  14.26 71.7 180 top
C338  *0.1u/16v_4  [C0402]  201.48 189.25 0 top
C339  *0.1u/16v_4  [C0402]  198.68 189.38 180 top
C340  10u/6.3v_6  [C0603]  201.48 191.92 180 top
C341  0.1u/16v_4  [C0402]  28 65.68 0 top
C343  0.1u/16v_4  [C0402]  28 66.57 0 top
C344  *ioac@1000p/50v_4  [C0402]  203.89 192.17 0 top
C345  *ioac@0.1u/16v_4  [C0402]  205.8 192.17 180 top
C346  *0.1u/16v_4  [C0402]  198.68 190.29 180 top
C347  *10u/6.3v_6  [C0603]  201.48 190.52 180 top
C348  0.1u/16v_4  [C0402]  162.1 75.46 0 top
C349  1u/6.3v_4  [C0402]  162.13 74.49 180 top
C350  *0.1u/16v_4  [C0402]  42.47 62.63 270 top
C351  6.8p/50v_4  [C0402]  154.49 107.21 90 bottom
C352  0.1u/16v_4  [C0402]  132.37 101.62 90 top
C353  0.1u/16v_4  [C0402]  81.84 87.9 180 bottom
C354  0.1u/16v_4  [C0402]  35.49 78.12 270 top
C355  0.1u/16v_4  [C0402]  37.27 78.12 270 top
C356  10u/6.3v_4  [C0402]  81.84 88.92 180 bottom
C357  *10p/50v_4  [C0402]  88.3 87.45 270 bottom
C360  10p/50v_4  [C0402]  81.84 89.81 180 bottom
C362  6.8p/50v_4  [C0402]  154.49 105.43 270 bottom
C363  0.1u/16v_4  [C0402]  41.71 68.04 0 top
C364  0.01u/50v/x7r_4  [C0402]  36.12 88.79 90 bottom
C365  0.1u/16v_4  [C0402]  34.3 78.15 270 top
C366  10u/6.3v_6  [C0603]  39.43 62.25 90 top
C367  0.1u/16v_4  [C0402]  43.36 62.63 270 top
C368  *ioac@1000p/50v_4  [C0402]  49.05 65.07 180 top
C369  typec@0.1u/16v_4_x7r  [C0402]  35.24 118.51 0 top
C370  0.1u/16v_4  [C0402]  41.59 62.63 90 top
C371  *for17@0.1u/16v_4  [C0402]  131.25 74.7 180 top
C373  *for17@10u/6.3v_4  [C0402]  131.25 73.81 180 top
C374  *10p/50v_4  [C0402]  88.3 85.67 90 bottom
C376  for17@10p/50v_4  [C0402]  131.25 75.58 180 top
C377  *0.1u/16v_4  [C0402]  40.7 62.63 270 top
C378  *for17@10p/50v_4  [C0402]  133.17 74.19 0 top
C379  *for17@10p/50v_4  [C0402]  135.24 74.21 0 top
C380  1u/6.3v_4  [C0402]  79.3 49.3 180 top
C381  1u/6.3v_4  [C0402]  77.4 48.28 180 top
C382  1u/6.3v_4  [C0402]  79.3 50.18 180 top
C383  *220p/50v_4  [C0402]  14.53 53.99 90 top
C386  0.1u/16v_4_x7r  [C0402]  20.76 43.33 90 top
C387  0.1u/16v_4  [C0402]  25.2 51.84 0 top
C389  0.1u/16v_4  [C0402]  25.2 50.82 0 top
C394  typec@0.1u/16v_4_x7r  [C0402]  37.27 115.46 0 top
C398  0.1u/16v_4  [C0402]  25.2 45.74 0 top
C405  0.1u/16v_4  [C0402]  25.2 44.72 0 top
C406  0.1u/16v_4  [C0402]  25.2 47.77 0 top
C407  0.1u/16v_4  [C0402]  25.2 46.76 0 top
C408  0.1u/16v_4  [C0402]  25.2 49.8 0 top
C411  0.1u/16v_4  [C0402]  25.2 48.79 0 top
C412  *gs@10u/6.3v_6  [C0603]  218.22 61.77 0 bottom
C413  0.1u/16v_4_x7r  [C0402]  22.92 52.98 180 top
C424  1u/6.3v_4  [C0402]  19.74 39.01 90 top
C425  *gs@22p/50v_4  [C0402]  220 48.05 0 bottom
C428  *gs@0.1u/16v_4  [C0402]  224.92 56.03 180 bottom
C431  *gs@33p/50v_4  [C0402]  221.04 62.5 270 bottom
C435  *0.1u/16v_4  [C0402]  224.34 44.47 90 bottom
C436  0.01u/50v_4  [C0402]  225.35 44.47 90 bottom
C437  0.01u/50v_4  [C0402]  223.45 44.47 90 bottom
C438  10u/6.3v_6  [C0603]  221.93 47.52 270 bottom
C450  0.1u/16v_4  [C0402]  19.74 36.85 90 top
C451  470p/50v_4  [C0402]  18.73 36.85 90 top
C452  100u/6.3v_1206  [C1206]  17.2 37.87 90 top
C453  *0.1u/16v_4  [C0402]  221.93 45.23 90 bottom
C454  *gs@33p/50v_4  [C0402]  224.92 57.93 180 bottom
C456  *10u/6.3v_4  [C0402]  213.92 41.78 90 bottom
C457  *100u/6.3v_3528  [C3528]  224.21 48.41 270 bottom
C458  *1.6p/50v_4  [C0402]  20.33 35 270 top
C459  0.1u/16v_4  [C0402]  23.5 34.59 0 top
C460  *1.6p/50v_4  [C0402]  20.33 33.19 90 top
C461  0.1u/16v_4  [C0402]  23.5 33.57 0 top
C462  0.1u/16v_4  [C0402]  16.06 32.91 270 top
C469  *1.6p/50v_4  [C0402]  23.04 30.88 90 top
C475  *1.6p/50v_4  [C0402]  23.04 29.1 270 top
C476  0.1u/16v_4  [C0402]  206.64 38.12 270 bottom
C477  100p/50v_4  [C0402]  208.59 38.12 90 bottom
C481  10u/6.3v_4  [C0402]  204.93 35.33 90 top
C482  0.1u/16v_4  [C0402]  189.79 39.01 180 bottom
C483  1u/10v_4  [C0402]  18.93 29.69 0 top
C484  10u/6.3v_4  [C0402]  200.34 38.75 0 bottom
C485  0.1u/16v_4  [C0402]  200.34 37.74 0 bottom
C487  100u/6.3v_1206  [C1206]  23.63 25.93 270 top
C488  10p/50v_4  [C0402]  202.49 39.9 270 bottom
C489  10u/6.3v_4  [C0402]  205.92 35.33 90 top
C490  *10p/50v_4  [C0402]  191.34 37.36 90 bottom
C491  1u/6.3v_4  [C0402]  189.79 35.96 0 bottom
C492  0.1u/16v_4  [C0402]  206.94 35.33 90 top
C493  *22p/50v_4  [C0402]  204.53 38.12 90 bottom
C494  *1u/10v_4  [C0402]  197.16 40.81 90 bottom
C495  0.1u/16v_4  [C0402]  169.73 32.66 270 bottom
C496  0.1u/16v_4  [C0402]  19.63 22.45 270 top
C497  470p/50v_4  [C0402]  18.3 22.28 180 top
C498  0.1u/16v_4  [C0402]  18.98 20.83 0 top
C499  0.1u/16v_4  [C0402]  18.98 19.87 0 top
C500  0.1u/16v_4  [C0402]  197.54 36.24 0 bottom
C501  10u/6.3v_4  [C0402]  197.54 35.35 0 bottom
C502  0.1u/16v_4  [C0402]  20.03 15.24 270 top
C504  0.01u/50v_4  [C0402]  224.47 37.74 270 bottom
C505  *1.6p/50v_4  [C0402]  17.96 17.04 0 top
C507  0.01u/50v_4  [C0402]  223.45 37.74 270 bottom
C508  0.1u/16v_4  [C0402]  180.14 45.61 270 bottom
C509  0.1u/16v_4  [C0402]  197.47 32 0 bottom
C510  10u/6.3v_4  [C0402]  197.47 32.96 0 bottom
C511  *1.6p/50v_4  [C0402]  19.74 17.04 180 top
C513  0.01u/50v_4  [C0402]  224.47 33.73 270 bottom
C514  0.1u/16v_4  [C0402]  185.15 45.59 270 bottom
C515  *10u/6.3v_6  [C0603]  199.8 24.25 180 bottom
C516  10u/6.3v_6  [C0603]  168.87 27.76 180 bottom
C517  *1.6p/50v_4  [C0402]  19.74 9.29 0 top
C518  *1.6p/50v_4  [C0402]  17.96 9.29 180 top
C519  10u/6.3v_4  [C0402]  209.86 32.13 180 bottom
C520  10u/6.3v_4  [C0402]  199.65 28.67 90 bottom
C522  0.01u/50v_4  [C0402]  223.45 33.73 270 bottom
C523  *10u/6.3v_6  [C0603]  206.81 24.58 0 bottom
C524  0.1u/16v_4  [C0402]  198.66 28.67 90 bottom
C525  *0.1u/16v_4  [C0402]  199.95 22.75 0 bottom
C526  *0.1u/16v_4  [C0402]  208.84 23.26 180 bottom
C527  10u/6.3v_4  [C0402]  201.4 26.79 90 bottom
C528  1u/6.3v_4  [C0402]  200.44 26.79 270 bottom
C529  10u/6.3v_4  [C0402]  199.47 26.79 90 bottom
C530  1u/6.3v_4  [C0402]  202.29 26.79 90 bottom
C532  0.1u/16v_4  [C0402]  206.81 27.27 180 bottom
C534  10u/6.3v_4  [C0402]  208.57 27.25 180 bottom
C535  2.2u/6.3v_4  [C0402]  205.54 27.02 270 bottom
C536  10u/6.3v_4  [C0402]  206.81 26.23 180 bottom
C537  *1000p/50v_4  [C0402]  211.51 33.29 180 bottom
C538  *0.1u/16v_4  [C0402]  206.81 33.19 0 top
C541  1u/6.3v_4  [C0402]  198.68 47.37 180 bottom
C545  *68p/50v_4  [C0402]  72.95 12.34 90 top
C546  *68p/50v_4  [C0402]  74.22 12.34 90 top
C547  100p/50v_4  [C0402]  208.97 15.13 180 bottom
C548  *68p/50v_4  [C0402]  75.49 12.34 90 top
C549  4.7u/6.3v_6  [C0603]  205.67 18.31 90 bottom
C550  100p/50v_4  [C0402]  208.77 10.59 180 bottom
C551  *68p/50v_4  [C0402]  76.76 12.34 90 top
C552  4.7u/6.3v_6  [C0603]  207.35 18.13 90 bottom
C553  100p/50v_4  [C0402]  208.77 11.7 0 bottom
C554  100p/50v_4  [C0402]  208.97 13.61 180 bottom
C555  39p/50v_4  [C0402]  57.56 20.75 90 top
C556  4.7u/10v_6  [C0603]  79.18 13.08 0 top
C577  0.1u/16v_4  [C0402]  119.64 170.38 0 top
C578  1000p/50v_4  [C0402]  119.64 169.36 0 top
C580  *1u/6.3v_4  [C0402]  118.75 164.92 0 bottom
C581  *1u/6.3v_4  [C0402]  118.75 165.93 180 bottom
C628  *0.1u/16v_4  [C0402]  99.37 137.94 0 top
C641  10u/6.3v_4  [C0402]  139.6 131.59 90 top
C642  10u/6.3v_4  [C0402]  135.77 131.59 90 top
C643  10u/6.3v_4  [C0402]  140.62 131.59 90 top
C645  d22@47u/6.3v_8  [C0805]  125.06 133.57 0 bottom
C647  10u/6.3v_4  [C0402]  127.56 141.37 90 top
C648  0.1u/16v_4  [C0402]  127.87 129.41 270 bottom
C649  0.1u/16v_4  [C0402]  128.83 129.41 270 bottom
C650  d22@47u/6.3v_8  [C0805]  125.06 129.41 0 bottom
C651  10u/6.3v_4  [C0402]  130.49 141.37 90 top
C652  ev@0.22u/10v_4  [C0402]  138.49 130.96 90 bottom
C653  ev@0.22u/10v_4  [C0402]  139.5 130.96 270 bottom
C654  ev@0.22u/10v_4  [C0402]  131.86 132.81 90 bottom
C655  ev@0.22u/10v_4  [C0402]  140.77 130.96 90 bottom
C656  ev@0.22u/10v_4  [C0402]  141.79 130.96 90 bottom
C657  10u/6.3v_4  [C0402]  129.47 141.37 90 top
C658  10p/50v_4  [C0402]  118.29 131.85 0 bottom
C659  d22@47u/6.3v_8  [C0805]  146.06 142.51 0 bottom
C660  ev@0.22u/10v_4  [C0402]  132.75 132.81 90 bottom
C661  ev@0.22u/10v_4  [C0402]  136.2 130.96 90 bottom
C662  ev@0.22u/10v_4  [C0402]  137.22 130.96 90 bottom
C663  10u/6.3v_4  [C0402]  120.96 130.07 0 bottom
C664  10u/6.3v_4  [C0402]  120.96 129.05 0 bottom
C665  10p/50v_4  [C0402]  116.39 131.85 180 bottom
C666  d22@47u/6.3v_8  [C0805]  125.06 131.49 0 bottom
C667  10u/6.3v_4  [C0402]  120.96 127.02 0 bottom
C668  0.1u/16v_4  [C0402]  127.79 133.34 270 bottom
C669  0.1u/16v_4  [C0402]  128.78 133.34 270 bottom
C672  1u/6.3v_4  [C0402]  146.61 116.81 90 bottom
C673  10u/6.3v_4  [C0402]  120.96 133.12 0 bottom
C674  10u/6.3v_4  [C0402]  120.96 131.08 0 bottom
C675  10u/6.3v_4  [C0402]  120.96 134.13 0 bottom
C676  10u/6.3v_4  [C0402]  128.45 141.37 90 top
C677  1u/6.3v_4  [C0402]  133.15 128.92 0 bottom
C678  10u/6.3v_4  [C0402]  120.96 128.04 0 bottom
C679  10u/6.3v_4  [C0402]  120.96 132.1 0 bottom
C680  *1u/6.3v_4  [C0402]  144.99 122.91 180 top
C681  gt3@1u/6.3v_4  [C0402]  87.79 116.15 90 top
C682  gt3@10u/6.3v_4  [C0402]  85.88 114.17 90 top
C683  gt3@1u/6.3v_4  [C0402]  88.78 114.17 270 top
C684  gt3@1u/6.3v_4  [C0402]  86.82 116.15 90 top
C685  gt3@1u/6.3v_4  [C0402]  88.75 116.15 90 top
C686  gt3@10u/6.3v_4  [C0402]  97.08 122.7 270 top
C687  gt3@10u/6.3v_4  [C0402]  98.61 122.7 270 top
C688  gt3@1u/6.3v_4  [C0402]  87.81 114.17 270 top
C689  gt3@1u/6.3v_4  [C0402]  86.85 114.17 270 top
C690  d22@47u/6.3v_8  [C0805]  80.14 127.6 180 bottom
C691  d10@22u/6.3v_6  [C0603]  93.91 113.18 270 bottom
C692  d10@22u/6.3v_6  [C0603]  93.78 118.64 90 bottom
C693  d10@22u/6.3v_6  [C0603]  90.79 115.34 180 top
C694  d10@22u/6.3v_6  [C0603]  90.79 116.78 180 top
C695  1u/6.3v_4  [C0402]  147.5 116.81 270 bottom
C696  d22@47u/6.3v_8  [C0805]  80.14 125.67 180 bottom
C697  d22@47u/6.3v_8  [C0805]  87.76 130.93 0 bottom
C698  1u/6.3v_4  [C0402]  144.46 127.93 90 bottom
C699  47u/6.3v_8  [C0805]  138.61 125.62 180 top
C700  1u/6.3v_4  [C0402]  76.92 96.29 90 top
C701  1u/6.3v_4  [C0402]  77.93 96.29 90 top
C702  d22@47u/6.3v_8  [C0805]  87.76 132.73 0 bottom
C703  d10@22u/6.3v_6  [C0603]  90.79 121.08 180 top
C704  d10@22u/6.3v_6  [C0603]  92.51 113.18 270 bottom
C705  d10@22u/6.3v_6  [C0603]  92.26 118.64 90 bottom
C706  d10@22u/6.3v_6  [C0603]  90.73 118.64 90 bottom
C707  d10@22u/6.3v_6  [C0603]  90.79 119.63 180 top
C708  gt3@10u/6.3v_4  [C0402]  80.83 101.21 180 top
C709  gt3@10u/6.3v_4  [C0402]  80.83 102.23 180 top
C710  1u/6.3v_4  [C0402]  83.29 113.43 180 top
C711  1u/6.3v_4  [C0402]  83.29 114.45 180 top
C712  1u/6.3v_4  [C0402]  146.16 107.84 0 bottom
C713  0.1u/16v_4  [C0402]  11.11 87.27 90 bottom
C714  1000p/50v_4  [C0402]  11.49 83.08 0 top
C716  *33p/50v_4  [C0402]  13.39 81.43 180 top
C718  *33p/50v_4  [C0402]  13.39 79.39 180 top
C719  *0.01u/50v_4  [C0402]  65.01 120.08 0 bottom
C720  0.1u/16v_4  [C0402]  13.34 87.85 90 bottom
C721  0.01u/50v_4  [C0402]  229.8 108.6 0 bottom
C723  2.2u_6  [C0603]  66.59 118.21 90 bottom
C724  1000p/50v_4  [C0402]  12.76 76.6 180 top
C726  0.01u/50v_4  [C0402]  229.8 109.62 0 bottom
C728  0.01u/50v_4  [C0402]  65.21 118.13 90 bottom
C730  *0.1u/16v_4  [C0402]  229.8 107.66 0 bottom
C731  0.1u/16v_4  [C0402]  198.68 191.26 0 top
C732  0.1u/16v_4  [C0402]  151.95 93.49 90 bottom
C733  *0.1u/16v_4  [C0402]  229.8 110.76 0 bottom
C735  0.1u/16v_4  [C0402]  201.48 188.23 180 top
C737  10u/6.3v_6  [C0603]  229.29 106.57 0 bottom
C739  22p/50v_4  [C0402]  129.6 93.24 90 bottom
C740  *100u/6.3v_3528  [C3528]  229.19 102.89 90 bottom
C742  *10p/50v_4  [C0402]  130.87 97.3 270 bottom
C743  0.01u/50v_4  [C0402]  229.88 99.77 0 bottom
C744  0.01u/50v_4  [C0402]  229.88 98.75 0 bottom
C746  1000p/3kv_1808  [CC1808]  29.65 93.49 0 bottom
C747  *22p/50v_4  [C0402]  179.86 50.16 90 top
C748  1u/6.3v_4  [C0402]  151.87 75.41 0 top
C749  0.01u/50v_4  [C0402]  228.91 84.86 0 bottom
C750  *0.1u/16v_4  [C0402]  129.09 100.73 0 top
C751  0.01u/50v_4  [C0402]  228.91 83.84 0 bottom
C752  *ioac@0.1u/25v_6  [C0603]  225.8 108.38 180 top
C753  0.1u/16v_4  [C0402]  198.68 192.2 0 top
C754  0.1u/16v_4  [C0402]  178.36 51.96 270 top
C755  0.1u/16v_4  [C0402]  198.68 188.36 0 top
C756  *ioac@1000p/50v_4  [C0402]  205.8 188.28 180 top
C757  0.1u/16v_4  [C0402]  39.3 78.12 270 top
C758  *1u/6.3v_4  [C0402]  29.6 73.6 90 top
C759  *ioac@0.1u/16v_4  [C0402]  203.89 188.28 0 top
C760  0.1u/16v_4  [C0402]  39.05 67.33 90 top
C761  *0.1u/16v_4  [C0402]  30.49 73.6 90 top
C762  0.1u/16v_4  [C0402]  43.11 77.08 270 top
C763  *0.1u/16v_4  [C0402]  200.72 185.57 0 bottom
C764  *0.1u/16v_4  [C0402]  219.89 72.54 90 top
C765  *0.1u/25v_6  [C0603]  219.39 67.84 180 top
C766  *tpm@0.1u/16v_4  [C0402]  168.61 67.79 180 bottom
C767  *tpm@10u/6.3v_6  [C0603]  168.51 66.52 180 bottom
C768  *tpm@0.1u/16v_4  [C0402]  171.18 75 270 bottom
C770  0.1u/16v_4  [C0402]  167.06 34.94 180 bottom
C771  0.1u/16v_4  [C0402]  178.26 25.83 0 bottom
C772  0.1u/16v_4  [C0402]  186.11 45.61 270 bottom
C774  *tpm@0.1u/16v_4  [C0402]  162.03 74.29 270 bottom
C775  *tpm@0.1u/16v_4  [C0402]  165.54 66.95 90 bottom
C776  *tpm@10u/6.3v_6  [C0603]  164.52 66.57 90 bottom
C777  0.1u/16v_4  [C0402]  184.23 45.59 270 bottom
C778  0.1u/16v_4  [C0402]  189.79 37.99 180 bottom
C780  0.1u/16v_4  [C0402]  189.79 31.9 180 bottom
C781  0.1u/16v_4  [C0402]  132.01 16.91 270 bottom
C783  0.1u/16v_4  [C0402]  134.3 16.78 0 bottom
C785  *0.1u/16v_4  [C0402]  218.07 37.13 90 bottom
C786  *1000p/50v_4  [C0402]  129.98 16.91 270 bottom
C787  *0.1u/16v_4  [C0402]  119.28 19.83 180 bottom
C788  *0.1u/16v_4  [C0402]  121.31 19.83 0 bottom
C790  0.22u/25v_6  [C0603]  130.45 11.96 90 bottom
C793  1u/6.3v_4  [C0402]  144.71 118.13 0 bottom
C794  *1u/6.3v_4  [C0402]  153.7 115.11 0 top
C796  180p/50v_4  [C0402]  172.04 45.59 270 bottom
C797  180p/50v_4  [C0402]  188.07 44.39 270 bottom
C798  180p/50v_4  [C0402]  170.74 27.2 270 bottom
C799  180p/50v_4  [C0402]  170.01 42.92 270 bottom
C800  180p/50v_4  [C0402]  189.79 28.85 0 bottom
C801  180p/50v_4  [C0402]  183.27 45.59 270 bottom
C802  *ioac@180p/50v_4  [C0402]  227.26 104.54 270 top
C803  180p/50v_4  [C0402]  133.66 178.89 0 bottom
C804  180p/50v_4  [C0402]  121.85 172.87 180 top
C805  180p/50v_4  [C0402]  149.54 19.58 90 bottom
C806  0.1u/16v_4  [C0402]  151.19 90.32 90 bottom
C807  *tpm@33p/50v_4  [C0402]  162.07 70.38 270 bottom
C808  0.1u/16v_4  [C0402]  86.54 121.94 270 bottom
C811  *0.1u/16v_4  [C0402]  174.81 54.81 180 bottom
C812  *0.1u/16v_4  [C0402]  195.28 33.47 180 bottom
C813  *0.1u/16v_4  [C0402]  157.41 35.2 180 bottom
C814  1000p/50v_4  [C0402]  102.04 132.23 270 top
C815  *1000p/50v_4  [C0402]  97.97 132.99 180 bottom
C816  *1000p/50v_4  [C0402]  102.27 133.17 0 bottom
C817  *1000p/50v_4  [C0402]  100.64 132.23 270 top
C818  *1000p/50v_4  [C0402]  103.69 132.23 270 top
C819  *1000p/50v_4  [C0402]  99.62 131.85 270 top
C821  180p/50v_4  [C0402]  201.1 179.22 0 bottom
C822  180p/50v_4  [C0402]  189.79 33.04 0 bottom
C823  *1000p/50v_4  [C0402]  88.7 121.94 270 bottom
C824  *1000p/50v_4  [C0402]  87.69 121.94 270 bottom
C963  ev@0.1u/16v_4  [C0402]  182.05 137.56 90 top
C965  ev@22u/6.3v_6  [C0603]  180.78 139.24 0 top
C1162  *150u/6.3v_3528  [C3528]  179 99.71 270 bottom
C1163  10u/6.3v_6  [C0603]  179.61 85.77 90 bottom
C1164  0.1u/10v_4  [C0402]  178.25 85.7 90 bottom
C1165  10u/6.3v_6  [C0603]  176.21 91.46 90 bottom
C1166  0.1u/10v_4  [C0402]  174.3 93.75 0 bottom
C1167  0.1u/10v_4  [C0402]  174.3 92.73 0 bottom
C1168  0.1u/10v_4  [C0402]  157.77 93.29 90 bottom
C1169  0.1u/10v_4  [C0402]  156.88 93.29 90 bottom
C1176  0.1u/10v_4  [C0402]  166.55 107.72 90 bottom
C1177  0.1u/10v_4  [C0402]  165.54 107.72 90 bottom
C1211  ev@0.1u/16v_4  [C0402]  190.68 139.21 180 top
C1212  ev@22u/6.3v_6  [C0603]  205.52 155.21 270 bottom
C1244  1u/6.3v_4  [C0402]  130.74 40.91 180 bottom
C1245  1u/6.3v_4  [C0402]  146.11 43.68 0 top
C1246  10u/6.3v_6  [C0603]  134.93 51.33 180 top
C1247  10u/6.3v_6  [C0603]  143.82 52.09 0 top
C1248  10u/6.3v_6  [C0603]  90.61 51.2 0 top
C1249  1u/6.3v_4  [C0402]  146.06 39.92 0 top
C1250  10u/6.3v_6  [C0603]  127.95 43.07 270 top
C1251  1u/6.3v_4  [C0402]  144.33 49.35 0 top
C1252  0.022u/25v_4  [C0402]  128.2 38.5 270 top
C1253  1u/6.3v_4  [C0402]  121.85 40.41 180 bottom
C1254  1u/6.3v_4  [C0402]  105.21 41.04 0 bottom
C1255  10u/6.3v_6  [C0603]  126.17 40.66 180 top
C1256  1u/6.3v_4  [C0402]  111.44 40.91 180 bottom
C1257  10u/6.3v_6  [C0603]  148.85 48.03 90 top
C1258  *0.1u/10v_4  [C0402]  109.61 44.65 270 top
C1259  0.1u/16v_4  [C0402]  125.91 41.8 180 top
C1260  1u/6.3v_4  [C0402]  139.5 40.53 90 bottom
C1261  1u/6.3v_4  [C0402]  101.15 41.04 180 bottom
C1262  10u/6.3v_6  [C0603]  124.01 43.33 90 top
C1263  10u/6.3v_6  [C0603]  93.83 50.95 0 top
C1264  10u/6.3v_6  [C0603]  113.7 60.04 180 top
C1265  10u/6.3v_6  [C0603]  148.37 51.07 180 top
C1266  0.1u/16v_4  [C0402]  148.04 49.96 0 top
C1267  0.1u/10v_4  [C0402]  148.67 52.09 180 top
C1270  10u/6.3v_6  [C0603]  146.31 41.07 0 top
C1271  1u/6.3v_4  [C0402]  98.38 39.97 0 bottom
C1272  10u/6.3v_6  [C0603]  139.5 53.49 90 top
C1273  1u/6.3v_4  [C0402]  115.12 40.91 0 bottom
C1275  1u/6.3v_4  [C0402]  144.33 47.92 0 top
C1308  10u/6.3v_6  [C0603]  134.32 61.61 270 top
C1309  1u/6.3v_4  [C0402]  112.25 41.09 180 top
C1310  1u/6.3v_4  [C0402]  146.49 53.99 0 top
C1311  1u/6.3v_4  [C0402]  146.49 55.01 0 top
C1312  10u/6.3v_6  [C0603]  95.33 55.24 0 top
C1313  10u/6.3v_6  [C0603]  114.33 67.1 180 top
C1314  1u/6.3v_4  [C0402]  126.93 66.57 270 bottom
C1315  1u/6.3v_4  [C0402]  146.49 56.03 0 top
C1317  *0.1u/10v_4  [C0402]  110.17 56.92 90 top
C1318  1u/6.3v_4  [C0402]  110.55 66.39 0 bottom
C1319  1u/6.3v_4  [C0402]  146.49 52.09 0 top
C1320  0.1u/16v_4  [C0402]  147.63 60.6 90 top
C1321  10u/6.3v_6  [C0603]  110.29 63.9 0 top
C1323  0.1u/16v_4  [C0402]  116.72 58.57 0 top
C1324  10u/6.3v_6  [C0603]  148.77 60.34 90 top
C1325  1u/6.3v_4  [C0402]  120.58 67.08 0 bottom
C1327  10u/6.3v_6  [C0603]  117.02 60.98 0 top
C1328  10u/6.3v_6  [C0603]  145.09 62.88 180 top
C1329  0.022u/25v_4  [C0402]  117.02 64.92 180 top
C1330  10u/6.3v_6  [C0603]  99.24 52.09 270 top
C1331  10u/6.3v_6  [C0603]  114.26 62.61 90 top
C1332  1u/6.3v_4  [C0402]  101.28 66.82 270 bottom
C1333  1u/6.3v_4  [C0402]  146.49 53.11 0 top
C1334  10u/6.3v_6  [C0603]  138.74 55.65 0 top
C1335  1u/6.3v_4  [C0402]  132.9 67.2 270 bottom
C1336  1u/6.3v_4  [C0402]  117.02 66.31 0 bottom
C1337  1u/6.3v_4  [C0402]  89.97 67.08 270 bottom
C1377  ev_a@0.1u/16v_4  [C0402]  175.57 155.72 90 top
C1386  ev_a@0.1u/16v_4  [C0402]  176.08 165.88 180 top
C1388  ev_b@0.1u/16v_4  [C0402]  209.1 121.56 180 top
C1391  ev_a@0.1u/16v_4  [C0402]  167.57 162.2 90 top
C1394  ev_a@1u/6.3v_4  [C0402]  200.46 155.72 270 top
C1396  ev_a@0.1u/16v_4  [C0402]  195.89 159.02 270 top
C1398  ev_a@1u/6.3v_4  [C0402]  179.51 154.96 270 top
C1399  ev_a@10u/6.3v_6  [C0603]  176.79 171.65 270 top
C1401  ev_a@1u/6.3v_4  [C0402]  167.7 155.85 90 top
C1402  ev_b@1u/6.3v_4  [C0402]  219.26 141.75 90 top
C1403  ev_b@1u/6.3v_4  [C0402]  219.64 148.61 270 top
C1408  ev_b@10u/6.3v_6  [C0603]  223.83 143.66 180 top
C1409  ev_b@820p/50v_4  [C0402]  213.54 112.41 90 bottom
C1413  ev_a@0.1u/16v_4  [C0402]  192.46 155.85 90 top
C1414  ev_b@0.1u/16v_4  [C0402]  216.34 145.94 180 top
C1415  ev_b@0.1u/16v_4  [C0402]  216.97 118.51 180 top
C1416  ev_b@820p/50v_4  [C0402]  212.78 153.82 270 bottom
C1418  ev_b@0.1u/16v_4  [C0402]  219.51 125.75 180 top
C1419  ev_b@0.1u/16v_4  [C0402]  211.18 149.78 180 top
C1420  ev_b@0.1u/16v_4  [C0402]  214.94 136.8 180 top
C1421  ev_b@1u/6.3v_4  [C0402]  219.39 129.56 0 top
C1422  ev_b@1u/6.3v_4  [C0402]  206.56 117.75 180 top
C1423  ev_b@0.1u/16v_4  [C0402]  215.7 122.57 0 top
C1432  ev_a@820p/50v_4  [C0402]  205.54 161.56 180 bottom
C1435  ev_a@0.1u/16v_4  [C0402]  173.03 156.61 90 top
C1436  ev_b@0.1u/16v_4  [C0402]  214.56 116.86 0 top
C1438  ev_b@1u/6.3v_4  [C0402]  206.56 137.94 180 top
C1439  ev_b@1u/6.3v_4  [C0402]  206.56 128.67 180 top
C1440  ev_a@0.1u/16v_4  [C0402]  200.59 166.77 90 top
C1447  ev_b@10u/6.3v_6  [C0603]  224.34 120.54 180 top
C1448  ev_a@1u/6.3v_4  [C0402]  167.57 167.41 90 top
C1450  ev_b@0.1u/16v_4  [C0402]  216.21 140.99 0 top
C1457  ev_b@1u/6.3v_4  [C0402]  206.56 149.75 180 top
C1458  ev_b@0.1u/16v_4  [C0402]  207.32 141.75 0 top
C1497  ev_a@0.1u/16v_4  [C0402]  174.55 158.9 270 top
C1498  ev_a@1u/6.3v_4  [C0402]  187.76 167.41 90 top
C1499  ev_a@0.1u/16v_4  [C0402]  191.57 167.91 270 top
C1504  ev_b@0.1u/16v_4  [C0402]  207.45 124.86 0 top
C1513  ev_b@1u/6.3v_4  [C0402]  219.39 117.62 0 top
C1537  ev_a@0.1u/16v_4  [C0402]  173.03 165.37 270 top
C1538  ev_a@1u/6.3v_4  [C0402]  187.89 155.85 270 top
C1543  ev_a@1u/6.3v_4  [C0402]  180.4 167.66 90 top
C1544  ev_b@0.1u/16v_4  [C0402]  207.32 145.18 0 top
C1549  ev_a@1u/6.3v_4  [C0402]  187.89 160.55 90 top
C1551  ev_a@820p/50v_4  [C0402]  165.16 161.94 0 top
C1764  ev_a@0.1u/16v_4  [C0402]  190.68 171.72 270 top
C3000  fpd@4.7u/6.3v_4  [C0402]  111.94 30.37 0 top
C3001  *fpd@2.2u/16v_6  [C0603]  114.23 35.45 0 top
C3002  fpd@0.01u/50v_4  [C0402]  111.82 18.94 270 bottom
C3007  fpd@0.01u/50v_4  [C0402]  112.83 24.15 0 bottom
C3008  fpd@0.1u/16v/x7r_4  [C0402]  112.83 25.42 0 bottom
C3224  0.1u/16v_4  [C0402]  128.71 175.41 315 bottom
C3225  0.1u/16v_4  [C0402]  129.34 176.04 315 bottom
C3226  0.1u/16v_4  [C0402]  130.87 177.57 315 bottom
C3227  0.1u/16v_4  [C0402]  130.23 176.93 315 bottom
C4000  ev@22u/6.3v_6  [C0603]  175.6 130.52 0 top
C4001  ev@22u/6.3v_6  [C0603]  172.36 135.66 180 top
C4002  ev@22u/6.3v_6  [C0603]  169.73 120.47 270 top
C4003  ev@22u/6.3v_6  [C0603]  175.72 135.35 0 top
C4004  ev@10u/6.3v_6  [C0603]  171.05 137.59 0 top
C4005  ev@10u/6.3v_6  [C0603]  172.43 132.35 0 top
C4006  ev@10u/6.3v_6  [C0603]  170.11 123.84 270 top
C4007  ev@10u/6.3v_6  [C0603]  172.3 134.13 0 top
C4008  ev@1u/6.3v_4  [C0402]  172.07 120.53 270 top
C4009  ev@1u/6.3v_4  [C0402]  175.47 132.93 0 top
C4010  ev@1u/6.3v_4  [C0402]  171.18 120.55 270 top
C4011  ev@1u/6.3v_4  [C0402]  175.95 136.54 0 top
C4012  ev@4.7u/10v_6  [C0603]  175.72 134.08 0 top
C4013  gc6@0.022u/25v_4  [C0402]  167.27 111.78 90 top
C4014  ev@4.7u/10v_6  [C0603]  175.6 131.79 0 top
C4015  ev@0.22u/10v_4  [C0402]  160.46 129.81 180 bottom
C4016  ev@0.22u/10v_4  [C0402]  160.46 128.92 180 bottom
C4017  ev@0.22u/10v_4  [C0402]  162.36 128.42 180 bottom
C4018  ev@0.22u/10v_4  [C0402]  162.36 127.53 180 bottom
C4019  gc6@0.022u/25v_4  [C0402]  166.3 111.78 270 top
C4020  ev@0.22u/10v_4  [C0402]  162.39 133.65 180 bottom
C4021  ev@0.22u/10v_4  [C0402]  162.39 132.76 180 bottom
C4022  ev@0.22u/10v_4  [C0402]  162.36 131.46 180 bottom
C4023  ev@0.22u/10v_4  [C0402]  162.36 130.58 180 bottom
C4024  gc6@0.1u/16v_4  [C0402]  214.06 106.05 270 bottom
C4025  gc6@0.1u/16v_4  [C0402]  220.03 106.05 0 bottom
C4026  ev@4.7u/6.3v_4  [C0402]  172.22 127 270 top
C4027  ev@1u/6.3v_4  [C0402]  173.16 127.01 90 top
C4028  ev@0.1u/16v_4  [C0402]  189.54 107.72 270 top
C4029  *ev@0.1u/16v_4  [C0402]  189.62 123.72 270 top
C4030  gc6@1000p/50v_4  [C0402]  208.22 107.2 180 bottom
C4031  *ev@0.1u/16v_4  [C0402]  188.65 125.37 90 top
C4032  ev@4.7u/6.3v_4  [C0402]  176.36 127.22 180 top
C4033  ev@1u/6.3v_4  [C0402]  178.49 127.4 180 top
C4034  ev@0.1u/16v_4  [C0402]  186.62 125.37 90 top
C4035  ev@0.1u/16v_4  [C0402]  187.64 125.37 90 top
C4036  ev@4.7u/6.3v_4  [C0402]  174.55 140.86 180 top
C4037  ev@1u/6.3v_4  [C0402]  175.72 138.72 0 top
C4038  ev@0.1u/16v_4  [C0402]  174.68 127.41 270 top
C4039  ev@4.7u/6.3v_4  [C0402]  176.71 128.16 180 top
C4040  ev@0.1u/16v_4  [C0402]  175.72 139.87 180 top
C4041  ev@4.7u/6.3v_4  [C0402]  196.88 107.94 0 top
C4100  ev@1u/6.3v_4  [C0402]  187.45 127.99 270 top
C4101  ev@1u/6.3v_4  [C0402]  184.36 139.03 270 top
C4102  ev@1u/6.3v_4  [C0402]  187.03 139.03 270 top
C4103  ev@1u/6.3v_4  [C0402]  185.76 139.03 270 top
C4104  ev@0.1u/16v_4  [C0402]  189.06 131.15 180 top
C4105  ev@0.1u/16v_4  [C0402]  189.06 130.14 180 top
C4106  ev@0.1u/16v_4  [C0402]  193.73 122.83 270 top
C4107  ev@0.1u/16v_4  [C0402]  188.27 138.83 270 top
C4108  ev@4.7u/6.3v_4  [C0402]  178.62 139.21 180 top
C4109  ev@4.7u/6.3v_4  [C0402]  189.64 125.9 270 top
C4110  ev@4.7u/6.3v_4  [C0402]  189.06 133.44 180 top
C4111  ev@10u/6.3v_6  [C0603]  179.76 171.72 90 top
C4112  ev@0.1u/16v_4  [C0402]  189.16 132.18 180 top
C4113  ev@4.7u/6.3v_4  [C0402]  177.35 139.34 270 top
C4115  ev@10u/6.3v_6  [C0603]  194.87 133.62 90 top
C4117  *ev@22u/6.3v_6  [C0603]  188.89 127.96 270 top
C4119  ev@22u/6.3v_6  [C0603]  183.06 138.7 270 top
C4200  ev@1000p/50v_4  [C0402]  176.21 106.83 90 bottom
C4201  *ev@1000p/50v_4  [C0402]  175.82 110.51 270 bottom
C4202  ev@1000p/50v_4  [C0402]  160.43 142.46 90 bottom
C4203  *ev@1000p/50v_4  [C0402]  162.49 142.13 0 bottom
C4204  ev@22u/6.3v_6  [C0603]  174.34 122.83 0 top
C4205  ev@0.1u/16v_4  [C0402]  177.12 125.57 90 top
C4206  ev@10p/50v_4c  [C0402]  192.92 114.62 90 bottom
C4207  ev@10p/50v_4c  [C0402]  194.19 114.6 90 bottom
C4208  ev@22u/6.3v_6  [C0603]  172.18 124.35 0 top
C4209  ev@4.7u/6.3v_4  [C0402]  174.05 124.62 270 top
C4210  ev@0.1u/16v_4  [C0402]  176.1 125.57 90 top
C4211  ev@0.1u/16v_4  [C0402]  175.09 125.57 90 top
C4400  ev@1u/6.3v_4  [C0402]  185.63 127.48 180 top
C4401  ev@1u/6.3v_4  [C0402]  178.9 126.25 180 top
C4402  ev@1u/6.3v_4  [C0402]  180.55 127.47 90 top
C4403  ev@1u/6.3v_4  [C0402]  187.08 129.84 0 top
C4404  ev@1u/6.3v_4  [C0402]  184.46 133.37 90 top
C4405  ev@1u/6.3v_4  [C0402]  178.9 130.27 180 top
C4406  ev@1u/6.3v_4  [C0402]  180.55 129.5 90 top
C4407  ev@1u/6.3v_4  [C0402]  177.75 131.71 90 top
C4408  ev@4.7u/10v_6  [C0603]  182.63 132.63 180 top
C4409  ev@4.7u/10v_6  [C0603]  183.29 124.23 180 top
C4410  ev@4.7u/10v_6  [C0603]  179.15 125.14 0 top
C4411  ev@4.7u/10v_6  [C0603]  182.17 134.89 90 top
C4412  ev@4.7u/10v_6  [C0603]  174.68 114.7 0 top
C4413  *ev@4.7u/10v_6  [C0603]  178.49 135.66 0 top
C4414  ev@4.7u/10v_6  [C0603]  179.13 116.1 180 top
C4415  ev@4.7u/10v_6  [C0603]  186.14 133.93 270 top
C4416  ev@4.7u/10v_6  [C0603]  184.69 129.64 0 top
C4417  *ev@4.7u/10v_6  [C0603]  173.79 119.91 0 top
C4418  ev@4.7u/10v_6  [C0603]  186.14 136.51 270 top
C4419  *ev@4.7u/10v_6  [C0603]  184.38 136.27 90 top
C4420  *ev@4.7u/10v_6  [C0603]  179.13 114.7 180 top
C4421  ev@4.7u/10v_6  [C0603]  178.49 134.39 0 top
C4422  ev@4.7u/10v_6  [C0603]  177.48 114.4 90 bottom
C4423  ev@22u/6.3v_6  [C0603]  182.35 130.53 90 top
C4424  ev@22u/6.3v_6  [C0603]  174.68 113.3 180 top
C4425  ev@22u/6.3v_6  [C0603]  179.61 131.41 180 top
C4426  ev@22u/6.3v_6  [C0603]  184.69 131.21 180 top
C4427  ev@22u/6.3v_6  [C0603]  179.13 113.3 0 top
C4428  ev@22u/6.3v_6  [C0603]  180.22 114.4 270 bottom
C4429  ev@22u/6.3v_6  [C0603]  176.1 114.4 270 bottom
C4430  ev@4.7u/10v_6  [C0603]  178.85 114.4 90 bottom
C4431  ev@4.7u/10v_6  [C0603]  174.68 111.91 0 top
C4432  *ev@4.7u/10v_6  [C0603]  174.73 114.4 90 bottom
C4433  ev@4.7u/10v_6  [C0603]  179.13 110.51 180 top
C4434  ev@4.7u/10v_6  [C0603]  179.13 111.91 180 top
C4435  ev@330u_2.5v_3528  [C3528]  172.65 117.24 0 top
C4596  1u/6.3v_4  [C0402]  31.81 71.27 90 top
C4597  *4.7u/6.3v_6  [C0603]  35.24 66.9 270 top
C4598  0.1u/16v_4  [C0402]  36.51 67.33 270 top
C4599  0.1u/16v_4  [C0402]  41.71 67.08 0 top
C4600  4.7u/6.3v_6  [C0603]  40.19 65.04 270 top
C4601  0.1u/16v_4  [C0402]  33 66.82 90 top
C4602  0.1u/16v_4  [C0402]  33.97 66.82 90 top
C4603  *10p/50v_4  [C0402]  43.49 71.29 180 top
C4604  *10p/50v_4  [C0402]  43.49 69.74 180 top
C4605  10p/50v_4  [C0402]  42.98 74.7 90 top
C4606  10p/50v_4  [C0402]  42.98 72.79 270 top
C4607  0.1u/16v_4_x7r  [C0402]  21.65 43.33 90 top
C4608  0.1u/16v_4_x7r  [C0402]  16.19 43.33 90 top
C4609  0.1u/16v_4_x7r  [C0402]  19.87 43.33 90 top
C4611  *10p/50v_4  [C0402]  29.01 24.66 180 top
C4612  *10p/50v_4  [C0402]  30.92 24.66 180 top
C4613  *10p/50v_4  [C0402]  42.22 24.66 0 top
C4614  *10p/50v_4  [C0402]  39.43 24.66 0 top
C4615  *10p/50v_4  [C0402]  44.76 24.53 0 top
C4616  10p/50v_4  [C0402]  32.82 25.55 0 top
C4617  0.1u/16v_4  [C0402]  34.73 25.04 270 top
C4618  4.7u/6.3v_6  [C0603]  35.87 25.29 90 top
C4647  typec@0.47u/25v_6  [C0603]  10.27 118.36 180 bottom
C4648  typec@0.47u/25v_6  [C0603]  10.78 114.98 0 top
C4649  typec@0.47u/25v_6  [C0603]  10.47 120.64 180 bottom
C4650  typec@0.47u/25v_6  [C0603]  10.93 116.73 0 bottom
C4664  0.1u/10v_4  [C0402]  163.38 107.59 90 bottom
C4665  0.1u/10v_4  [C0402]  162.49 107.59 90 bottom
C4711  47u/6.3v_8  [C0805]  213.92 29.23 0 bottom
C4712  100u/6.3v_1206  [C1206]  214.43 27.2 0 bottom
C4713  470p/50v_4  [C0402]  210.37 27.53 180 bottom
C4714  1u/6.3v_4  [C0402]  215.93 30.25 90 bottom
C4715  0.1u/16v_4  [C0402]  214 30.8 0 bottom
C4723  *22p/50v_4  [C0402]  153.07 95.75 90 bottom
C4726  *22p/50v_4  [C0402]  175.09 47.9 90 bottom
C4727  0.1u/10v_4  [C0402]  155.58 62.45 180 top
C4728  10u/6.3v_6  [C0402]  155.58 61.44 180 top
C4733  *for15@10p/50v_4  [C0402]  170.24 84.86 270 bottom
C4734  *for15@10u/6.3v_4  [C0402]  172.27 84.86 270 bottom
C4735  *for15@0.1u/16v_4  [C0402]  171.25 84.86 270 bottom
